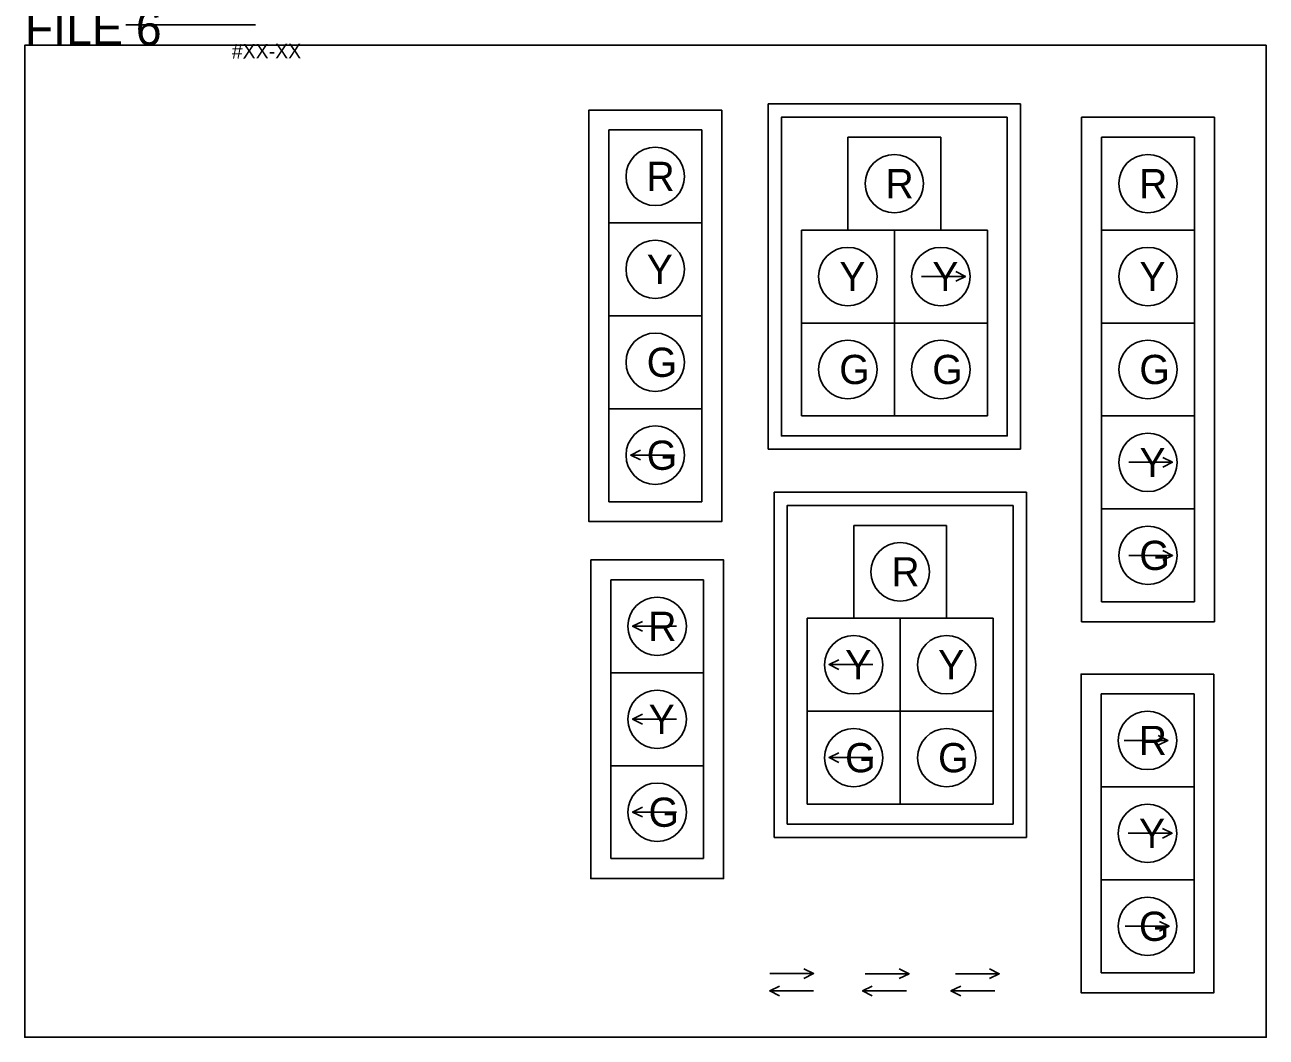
# Model space of a CAD drawing. Extents: x -218554 to 420114, y -565956 to -483460.
# Drawn here: x 418532.3 to 418770.6, y -565852.1 to -565657.6 of the extents above; entities that cross this region are included whole.
import ezdxf

# ---------------------------------------------------------------- set-up
doc = ezdxf.new("R2010")
doc.units = 0
for name, color, linetype in [('C-ANNO-TEXT', 7, 'Continuous'), ('Level 1', 7, 'Continuous'), ('Level 61', 7, 'Continuous'), ('Template', 7, 'Continuous')]:
    doc.layers.add(name, color=color, linetype=linetype)

msp = doc.modelspace()

# ---------------------------------------------------------------- linework, layer by layer
at = {"layer": 'Level 1'}
msp.add_line((418551.64, -565657.63), (418576.54, -565657.63), dxfattribs=at)
at = {"layer": 'Level 61'}
for p, q in [((418723.44, -565672.84), (418674.99, -565672.84)), ((418674.99, -565672.84), (418674.99, -565739.14)), ((418723.44, -565739.14), (418723.44, -565672.84)), ((418644.39, -565677.82), (418662.24, -565677.82)), ((418644.39, -565677.82), (418644.39, -565695.67)), ((418662.24, -565677.82), (418662.24, -565695.67)), ((418708.14, -565679.21), (418690.29, -565679.21)), ((418690.29, -565679.21), (418690.29, -565697.06)), ((418708.14, -565679.21), (418708.14, -565697.06)), ((418738.98, -565679.21), (418756.83, -565679.21)), ((418738.98, -565679.21), (418738.98, -565697.06)), ((418756.83, -565679.21), (418756.83, -565697.06)), ((418644.39, -565695.67), (418662.24, -565695.67)), ((418644.39, -565695.67), (418644.39, -565713.53)), ((418662.24, -565695.67), (418662.24, -565713.53)), ((418699.22, -565697.06), (418681.37, -565697.06)), ((418681.37, -565697.06), (418681.37, -565714.91)), ((418699.22, -565697.06), (418699.22, -565714.91)), ((418717.07, -565697.06), (418699.22, -565697.06)), ((418699.22, -565697.06), (418699.22, -565714.91)), ((418717.07, -565697.06), (418717.07, -565714.91)), ((418738.98, -565697.06), (418756.83, -565697.06)), ((418738.98, -565697.06), (418738.98, -565714.91)), ((418756.83, -565697.06), (418756.83, -565714.91)), ((418704.45, -565705.97), (418712.86, -565705.97)), ((418644.39, -565713.53), (418662.24, -565713.53)), ((418644.39, -565713.53), (418644.39, -565731.38)), ((418662.24, -565713.53), (418662.24, -565731.38)), ((418699.22, -565714.91), (418681.37, -565714.91)), ((418681.37, -565714.91), (418681.37, -565732.77)), ((418717.07, -565714.91), (418699.22, -565714.91)), ((418699.22, -565714.91), (418699.22, -565732.77)), ((418699.22, -565714.91), (418699.22, -565732.77)), ((418717.07, -565714.91), (418717.07, -565732.77)), ((418738.98, -565714.91), (418756.83, -565714.91)), ((418738.98, -565714.91), (418738.98, -565732.77)), ((418756.83, -565714.91), (418756.83, -565732.77)), ((418644.39, -565731.38), (418662.24, -565731.38)), ((418644.39, -565731.38), (418644.39, -565749.23)), ((418662.24, -565731.38), (418662.24, -565749.23)), ((418699.22, -565732.77), (418681.37, -565732.77)), ((418717.07, -565732.77), (418699.22, -565732.77)), ((418756.83, -565732.77), (418738.98, -565732.77)), ((418738.98, -565732.77), (418738.98, -565750.62)), ((418741.36, -565732.77), (418754.45, -565732.77)), ((418756.83, -565732.77), (418756.83, -565750.62)), ((418674.99, -565739.14), (418723.44, -565739.14)), ((418657.01, -565740.28), (418648.6, -565740.28)), ((418744.21, -565741.67), (418752.62, -565741.67)), ((418724.56, -565747.41), (418676.11, -565747.41)), ((418676.11, -565747.41), (418676.11, -565813.71)), ((418724.56, -565813.71), (418724.56, -565747.41)), ((418644.39, -565749.23), (418662.24, -565749.23)), ((418756.83, -565750.62), (418738.98, -565750.62)), ((418738.98, -565750.62), (418738.98, -565768.47)), ((418756.83, -565750.62), (418756.83, -565768.47)), ((418691.41, -565753.78), (418709.26, -565753.78)), ((418691.41, -565753.78), (418691.41, -565771.63)), ((418709.26, -565753.78), (418709.26, -565771.63)), ((418744.22, -565759.54), (418752.63, -565759.54)), ((418644.75, -565764.25), (418662.6, -565764.25)), ((418644.75, -565764.25), (418644.75, -565782.1)), ((418662.6, -565764.25), (418662.6, -565782.1)), ((418756.83, -565768.47), (418738.98, -565768.47)), ((418682.48, -565771.63), (418682.48, -565789.48)), ((418682.48, -565771.63), (418700.33, -565771.63)), ((418700.33, -565771.63), (418700.33, -565789.48)), ((418700.33, -565771.63), (418718.18, -565771.63)), ((418700.33, -565771.63), (418700.33, -565789.48)), ((418718.18, -565771.63), (418718.18, -565789.48)), ((418657.37, -565773.15), (418648.96, -565773.15)), ((418644.75, -565782.1), (418662.6, -565782.1)), ((418644.75, -565782.1), (418644.75, -565799.95)), ((418662.6, -565782.1), (418662.6, -565799.95)), ((418695.11, -565780.53), (418686.69, -565780.53)), ((418756.75, -565786.17), (418738.9, -565786.17)), ((418738.9, -565786.17), (418738.9, -565804.02)), ((418756.75, -565786.17), (418756.75, -565804.02)), ((418682.48, -565789.48), (418700.33, -565789.48)), ((418682.48, -565789.48), (418682.48, -565807.33)), ((418700.33, -565789.48), (418700.33, -565807.33)), ((418700.33, -565789.48), (418718.18, -565789.48)), ((418700.33, -565789.48), (418700.33, -565807.33)), ((418718.18, -565789.48), (418718.18, -565807.33)), ((418657.37, -565791), (418648.96, -565791)), ((418743.31, -565795.09), (418751.73, -565795.09)), ((418695.11, -565798.38), (418686.69, -565798.38)), ((418644.75, -565799.95), (418662.6, -565799.95)), ((418644.75, -565799.95), (418644.75, -565817.8)), ((418662.6, -565799.95), (418662.6, -565817.8)), ((418756.75, -565804.02), (418738.9, -565804.02)), ((418738.9, -565804.02), (418738.9, -565821.87)), ((418756.75, -565804.02), (418756.75, -565821.87)), ((418682.48, -565807.33), (418700.33, -565807.33)), ((418700.33, -565807.33), (418718.18, -565807.33)), ((418657.37, -565808.85), (418648.96, -565808.85)), ((418744.13, -565812.92), (418752.54, -565812.92)), ((418676.11, -565813.71), (418724.56, -565813.71)), ((418644.75, -565817.8), (418662.6, -565817.8)), ((418756.75, -565821.87), (418738.9, -565821.87)), ((418738.9, -565821.87), (418738.9, -565839.72)), ((418756.75, -565821.87), (418756.75, -565839.72)), ((418743.55, -565830.79), (418751.97, -565830.79)), ((418675.28, -565839.87), (418683.7, -565839.87)), ((418693.62, -565839.9), (418702.03, -565839.9)), ((418710.96, -565839.92), (418719.37, -565839.92)), ((418756.75, -565839.72), (418738.9, -565839.72)), ((418683.7, -565843.2), (418675.28, -565843.2)), ((418701.53, -565843.2), (418693.11, -565843.2)), ((418718.5, -565843.2), (418710.09, -565843.2))]:
    msp.add_line(p, q, dxfattribs=at)
for points in [[(418666.07, -565674), (418640.56, -565674), (418640.56, -565753.05), (418666.07, -565753.05)], [(418720.89, -565675.39), (418677.54, -565675.39), (418677.54, -565736.59), (418720.89, -565736.59)], [(418760.66, -565675.39), (418735.16, -565675.39), (418735.16, -565772.29), (418760.66, -565772.29)], [(418722.01, -565749.96), (418678.66, -565749.96), (418678.66, -565811.16), (418722.01, -565811.16)], [(418640.92, -565760.42), (418666.42, -565760.42), (418666.42, -565821.63), (418640.92, -565821.63)], [(418760.58, -565782.34), (418735.07, -565782.34), (418735.07, -565843.55), (418760.58, -565843.55)]]:
    msp.add_lwpolyline(points, close=True, dxfattribs=at)
for points in [[(418710.99, -565705.03), (418712.86, -565705.97), (418710.99, -565706.9)], [(418650.47, -565739.34), (418648.6, -565740.28), (418650.47, -565741.21)], [(418750.75, -565740.73), (418752.62, -565741.67), (418750.75, -565742.6)], [(418750.76, -565758.61), (418752.63, -565759.54), (418750.76, -565760.48)], [(418650.83, -565772.22), (418648.96, -565773.15), (418650.83, -565774.09)], [(418688.56, -565779.6), (418686.69, -565780.53), (418688.56, -565781.47)], [(418650.83, -565790.07), (418648.96, -565791), (418650.83, -565791.94)], [(418749.86, -565796.03), (418751.73, -565795.09), (418749.86, -565794.16)], [(418688.56, -565797.45), (418686.69, -565798.38), (418688.56, -565799.32)], [(418650.83, -565807.92), (418648.96, -565808.85), (418650.83, -565809.79)], [(418750.67, -565811.98), (418752.54, -565812.92), (418750.67, -565813.85)], [(418750.1, -565829.86), (418751.97, -565830.79), (418750.1, -565831.73)], [(418681.83, -565840.81), (418683.7, -565839.87), (418681.83, -565838.94)], [(418700.16, -565838.96), (418702.03, -565839.9), (418700.16, -565840.83)], [(418717.5, -565838.99), (418719.37, -565839.92), (418717.5, -565840.85)], [(418677.15, -565842.27), (418675.28, -565843.2), (418677.15, -565844.14)], [(418694.98, -565842.27), (418693.11, -565843.2), (418694.98, -565844.14)], [(418711.96, -565842.27), (418710.09, -565843.2), (418711.96, -565844.14)]]:
    msp.add_lwpolyline(points, dxfattribs=at)
for centre in [(418653.31, -565686.75), (418699.22, -565688.14), (418747.91, -565688.14), (418653.31, -565704.6), (418690.29, -565705.99), (418708.14, -565705.99), (418747.91, -565705.99), (418653.31, -565722.45), (418690.29, -565723.84), (418708.14, -565723.84), (418747.91, -565723.84), (418653.31, -565740.3), (418747.91, -565741.69), (418747.91, -565759.54), (418700.33, -565762.71), (418653.67, -565773.17), (418691.41, -565780.56), (418709.26, -565780.56), (418653.67, -565791.03), (418747.83, -565795.09), (418691.41, -565798.41), (418709.26, -565798.41), (418653.67, -565808.88), (418747.83, -565812.94), (418747.83, -565830.79)]:
    msp.add_circle(centre, 5.61, dxfattribs=at)
at = {"layer": 'Template'}
msp.add_lwpolyline([(418770.61, -565661.57), (418532.27, -565661.57), (418532.27, -565852.09), (418770.61, -565852.09)], close=True, dxfattribs=at)

# ---------------------------------------------------------------- texts
at = {"layer": 'C-ANNO-TEXT'}
msp.add_text('#XX-XX ', height=2.8, rotation=0.2455, dxfattribs=at).set_placement((418572.01, -565664.12))
at = {"layer": 'Level 61'}
for s, p in [('R', (418651.62, -565689.55)), ('R', (418697.52, -565690.94)), ('R', (418746.21, -565690.94)), ('Y', (418651.68, -565707.4)), ('Y', (418688.66, -565708.79)), ('Y', (418706.51, -565708.79)), ('Y', (418746.28, -565708.79)), ('G', (418651.67, -565725.26)), ('G', (418688.64, -565726.64)), ('G', (418706.5, -565726.64)), ('G', (418746.26, -565726.64)), ('G', (418651.67, -565743.11)), ('Y', (418746.28, -565744.5)), ('G', (418746.26, -565762.35)), ('R', (418698.64, -565765.51)), ('R', (418651.97, -565775.98)), ('Y', (418689.78, -565783.36)), ('Y', (418707.63, -565783.36)), ('Y', (418652.04, -565793.83)), ('R', (418746.13, -565797.9)), ('G', (418689.76, -565801.21)), ('G', (418707.61, -565801.21)), ('G', (418652.02, -565811.68)), ('Y', (418746.19, -565815.75)), ('G', (418746.18, -565833.6))]:
    msp.add_text(s, height=5.61, dxfattribs=at).set_placement(p)
at = {"layer": 'Template'}
msp.add_text('FILE 6', height=6.667, rotation=360, dxfattribs=at).set_placement((418532.27, -565661.57))

doc.saveas('drawing.dxf')
